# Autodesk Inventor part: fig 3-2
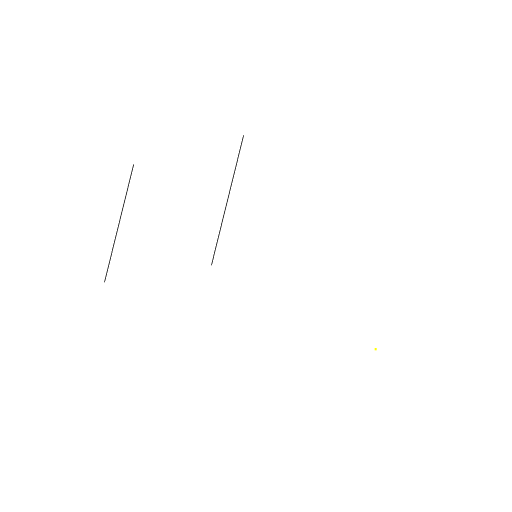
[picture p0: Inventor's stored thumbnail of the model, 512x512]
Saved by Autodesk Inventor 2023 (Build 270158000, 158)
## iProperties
Created: 2011-07
Part Number: fig 3-2
Material: Generic
Document SubType Name: Modeling
Designer: CadCim
Density: 1 g/cm^3
Appearance: Default
Author: CadCim
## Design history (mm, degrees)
sketch "Sketch1"
  geometry: L1 (-29, 4)-(-20, -8); L2 (-16, -0.965)-(-25.943, 12.292); 1 further point
  constraints: 4 end point, 1 parallel, 1 other
